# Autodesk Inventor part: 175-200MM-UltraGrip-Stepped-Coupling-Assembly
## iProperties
Created: 2012-05
Part Number: 175-200MM-UltraGrip-Stepped-Coupling-Assembly
Document SubType Name: Modeling
Designer: D Cole
Density: 1 g/cm^3
Author: D Cole
